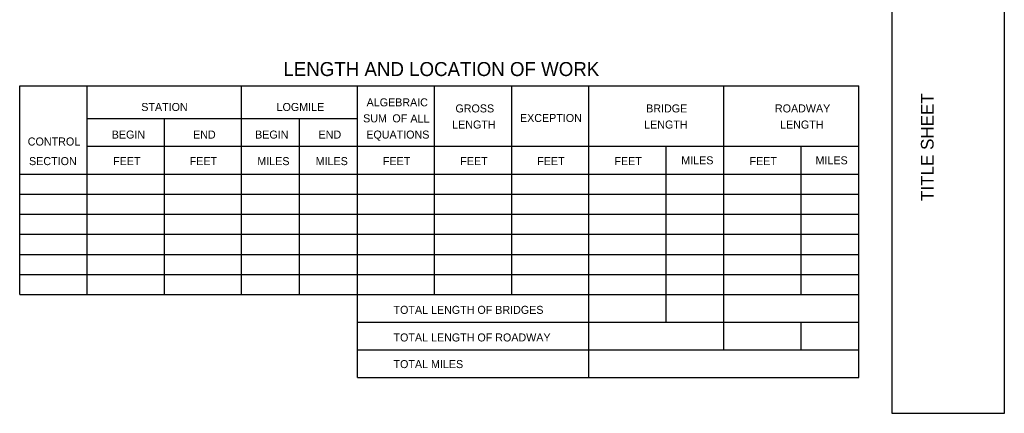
# Model space of a CAD drawing. Extents: x 0.19 to 2.82, y 0.04 to 1.79.
# Drawn here: x 1.796 to 2.817, y 0.042 to 0.449 of the extents above; entities that cross this region are included whole.
import ezdxf

# ---------------------------------------------------------------- set-up
doc = ezdxf.new("R2010")
doc.units = 0
doc.layers.add('Annotation', color=7, linetype='Continuous')
doc.layers.add('Standard Info', color=7, linetype='Continuous')

msp = doc.modelspace()

# ---------------------------------------------------------------- linework, layer by layer
at = {"layer": 'Annotation'}
msp.add_lwpolyline([(2.7, 0.0417), (2.8167, 0.0417), (2.8167, 1.7916), (2.7, 1.7916)], close=True, dxfattribs=at)
at = {"layer": 'Standard Info'}
for p, q in [((1.796, 0.3809), (2.666, 0.3809)), ((1.796, 0.1646), (1.796, 0.3809)), ((1.866, 0.1646), (1.866, 0.3809)), ((2.026, 0.1646), (2.026, 0.3809)), ((2.146, 0.0787), (2.146, 0.3809)), ((2.226, 0.1646), (2.226, 0.3809)), ((2.306, 0.1646), (2.306, 0.3809)), ((2.386, 0.0787), (2.386, 0.3809)), ((2.526, 0.1075), (2.526, 0.3809)), ((2.666, 0.0787), (2.666, 0.3809)), ((1.866, 0.3471), (2.146, 0.3471)), ((1.946, 0.1646), (1.946, 0.3471)), ((2.086, 0.1646), (2.086, 0.3471)), ((1.866, 0.3184), (2.666, 0.3184)), ((2.466, 0.136), (2.466, 0.3184)), ((2.606, 0.1646), (2.606, 0.3184)), ((1.796, 0.2896), (2.666, 0.2896)), ((1.796, 0.2688), (2.666, 0.2688)), ((1.796, 0.248), (2.666, 0.248)), ((1.796, 0.2271), (2.666, 0.2271)), ((1.796, 0.2063), (2.666, 0.2063)), ((1.796, 0.1855), (2.666, 0.1855)), ((1.796, 0.1646), (2.666, 0.1646)), ((2.146, 0.136), (2.666, 0.136)), ((2.606, 0.1075), (2.606, 0.136)), ((2.146, 0.1075), (2.666, 0.1075)), ((2.146, 0.0787), (2.666, 0.0787))]:
    msp.add_line(p, q, dxfattribs=at)

# ---------------------------------------------------------------- texts
at = {"layer": 'Annotation'}
msp.add_text('           TITLE SHEET           ', height=0.013166, rotation=90, dxfattribs=at).set_placement((2.7434, 0.2079))
at = {"layer": 'Standard Info'}
for s, height, p in [('LENGTH AND LOCATION OF WORK', 0.0145, (2.0693, 0.3911)), ('ALGEBRAIC', 0.0083, (2.1556, 0.3597)), ('STATION', 0.0083, (1.922, 0.3549)), ('LOGMILE', 0.0083, (2.0623, 0.3549)), ('GROSS', 0.0083, (2.2477, 0.3534)), ('BRIDGE', 0.0083, (2.4454, 0.3534)), ('ROADWAY', 0.0083, (2.5789, 0.3534)), ('SUM', 0.0083, (2.152, 0.3431)), ('OF', 0.00833, (2.1823, 0.3431)), ('ALL', 0.00833, (2.201, 0.3429)), ('EXCEPTION', 0.0083, (2.3146, 0.3435)), ('LENGTH', 0.0083, (2.2443, 0.3367)), ('LENGTH', 0.0083, (2.4433, 0.3367)), ('LENGTH', 0.0083, (2.5842, 0.3367)), ('CONTROL', 0.00833, (1.8043, 0.3191)), ('BEGIN', 0.0083, (1.8914, 0.3263)), ('END', 0.0083, (1.9757, 0.3263)), ('BEGIN', 0.0083, (2.04, 0.3263)), ('END', 0.0083, (2.1058, 0.3263)), ('EQUATIONS', 0.0083, (2.1553, 0.3263)), ('SECTION', 0.00833, (1.8056, 0.2988)), ('FEET', 0.0083, (1.8928, 0.2988)), ('FEET', 0.0083, (1.9722, 0.2988)), ('MILES', 0.0083, (2.0423, 0.2988)), ('MILES', 0.0083, (2.1028, 0.2988)), ('FEET', 0.0083, (2.1725, 0.2988)), ('FEET', 0.0083, (2.2527, 0.2988)), ('FEET', 0.0083, (2.3325, 0.2988)), ('FEET', 0.0083, (2.4125, 0.2988)), ('MILES', 0.0083, (2.4818, 0.2996)), ('FEET', 0.0083, (2.5526, 0.2988)), ('MILES', 0.0083, (2.621, 0.2996)), ('TOTAL LENGTH OF BRIDGES', 0.0083, (2.1835, 0.1447)), ('TOTAL LENGTH OF ROADWAY', 0.0083, (2.1835, 0.1161)), ('TOTAL MILES', 0.0083, (2.1835, 0.0885))]:
    msp.add_text(s, height=height, dxfattribs=at).set_placement(p)

doc.saveas('drawing.dxf')
